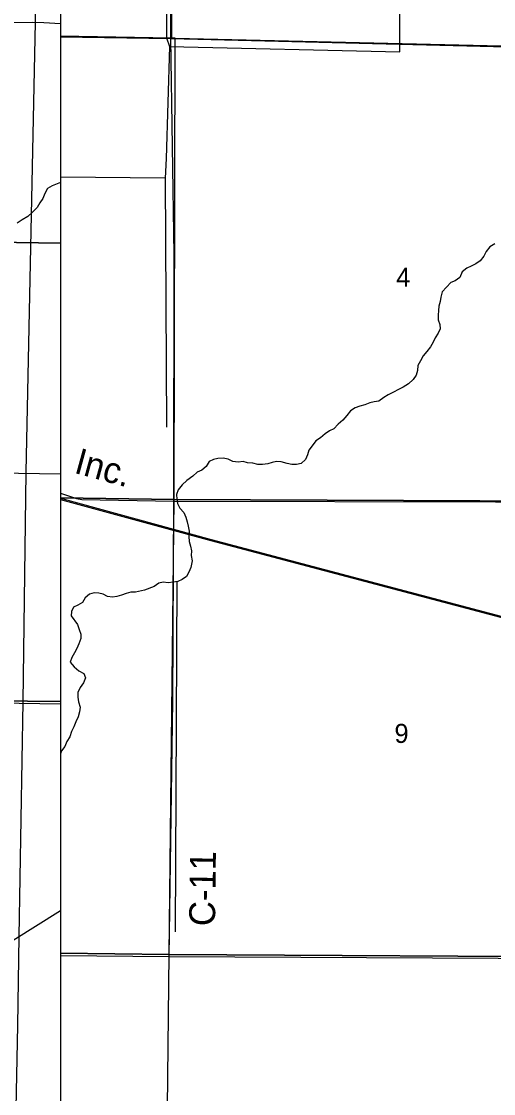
# Model space of a CAD drawing. Extents: x -6.2 to 37.4, y 0.2 to 22.2.
# Drawn here: x 5.038 to 5.556, y 16.426 to 17.601 of the extents above; entities that cross this region are included whole.
import ezdxf

# ---------------------------------------------------------------- set-up
doc = ezdxf.new("R2010")
doc.units = 0
for name, color, linetype in [('GM_X_County_Road', 7, 'Continuous'), ('GM_X_County_Road_Text', 7, 'Continuous'), ('GM_X_Minor_River', 7, 'Continuous'), ('GM_X_Rail_Line', 7, 'Continuous'), ('GM_X_Rail_Line_Text', 7, 'Continuous'), ('GM_X_Section', 7, 'Continuous'), ('GM_X_Section_Text', 7, 'Continuous'), ('GM_X_State_Route', 7, 'Continuous'), ('GM_X_Township_Road', 7, 'Continuous'), ('GM_X_US_Shield', 7, 'Continuous'), ('SH_Border', 7, 'Continuous'), ('SH_Cut_Line', 7, 'Continuous')]:
    doc.layers.add(name, color=color, linetype=linetype)

msp = doc.modelspace()

# ---------------------------------------------------------------- linework, layer by layer
at = {"layer": 'GM_X_County_Road'}
for points in [[(5.2003, 16.5759), (5.204, 16.8564), (5.2054, 17.0752), (5.2057, 17.3456), (5.202, 17.5822)], [(5.0809, 17.0839), (5.0987, 17.078), (5.1044, 17.077), (5.2054, 17.0752)], [(5.2054, 17.0752), (5.5577, 17.0744), (5.7084, 17.0732), (5.9545, 17.0713), (6.206, 17.0692)], [(4.5241, 16.8594), (4.5391, 16.8592), (4.8996, 16.8558), (5.0809, 16.853)]]:
    msp.add_lwpolyline(points, dxfattribs=at)
at = {"layer": 'GM_X_Minor_River'}
msp.add_line((5.1958, 17.4293), (5.0809, 17.4303), dxfattribs=at)
for points in [[(5.1975, 17.7074), (5.1971, 17.5832), (5.2004, 17.5735), (5.4528, 17.5676), (5.4532, 17.7074)], [(5.2004, 17.5735), (5.1968, 17.4509)], [(5.1968, 17.4509), (5.1958, 17.4293), (5.1973, 17.1562)], [(5.0809, 17.4246), (5.0773, 17.423), (5.0721, 17.421), (5.0668, 17.4179), (5.064, 17.4124), (5.0616, 17.4071), (5.0583, 17.4021), (5.0555, 17.397), (5.0505, 17.3918), (5.0451, 17.3874), (5.0392, 17.3837), (5.0336, 17.38)], [(5.5572, 17.3571), (5.5516, 17.354), (5.5474, 17.349), (5.545, 17.3437), (5.5409, 17.3387), (5.5361, 17.3352), (5.5311, 17.3328), (5.5263, 17.3304), (5.5213, 17.3266), (5.5185, 17.3205), (5.5136, 17.3167), (5.5087, 17.3147), (5.504, 17.3098), (5.4993, 17.3048), (5.4979, 17.2989), (5.497, 17.294), (5.4956, 17.2891), (5.4953, 17.284), (5.4948, 17.2789), (5.4951, 17.274), (5.4969, 17.269), (5.4972, 17.2642), (5.4948, 17.2592), (5.4917, 17.2543), (5.4895, 17.2494), (5.4865, 17.2443), (5.4824, 17.2393), (5.4785, 17.2344), (5.4756, 17.229), (5.4728, 17.2237), (5.4721, 17.2183), (5.4709, 17.2133), (5.4676, 17.2085), (5.4625, 17.2038), (5.4564, 17.2002), (5.4516, 17.1976), (5.4458, 17.1947), (5.4402, 17.1918), (5.4354, 17.1888), (5.43, 17.1849), (5.4247, 17.1839), (5.4199, 17.1831), (5.4146, 17.1807), (5.409, 17.1793), (5.4038, 17.1773), (5.399, 17.174), (5.3947, 17.169), (5.3903, 17.1639), (5.3854, 17.1597), (5.3806, 17.1546), (5.3758, 17.1523), (5.371, 17.1489), (5.3658, 17.1445), (5.3609, 17.1412), (5.357, 17.1359), (5.3533, 17.1309), (5.3517, 17.126), (5.3497, 17.1209), (5.3447, 17.1165), (5.3397, 17.1154), (5.3344, 17.1155), (5.3295, 17.1164), (5.3227, 17.1182), (5.3179, 17.1185), (5.313, 17.1177), (5.3082, 17.1159), (5.3026, 17.1152), (5.2973, 17.1155), (5.2918, 17.1168), (5.286, 17.1171), (5.2811, 17.1187), (5.2759, 17.118), (5.27, 17.1187), (5.2648, 17.1211), (5.2593, 17.1223)], [(5.2593, 17.1223), (5.2534, 17.1219), (5.2486, 17.1207), (5.2438, 17.1185), (5.2408, 17.113), (5.2358, 17.1093), (5.231, 17.107), (5.226, 17.1027), (5.2196, 17.0979), (5.2144, 17.0929), (5.2101, 17.0875), (5.2083, 17.0824), (5.2084, 17.0772), (5.2091, 17.0725), (5.2118, 17.0675), (5.2161, 17.0627), (5.2184, 17.0575), (5.2197, 17.0525), (5.2209, 17.0478), (5.2221, 17.0424), (5.2218, 17.0364), (5.2219, 17.0309), (5.2237, 17.0259), (5.2245, 17.0206), (5.2242, 17.0156), (5.2253, 17.0097), (5.2238, 17.0024), (5.2218, 16.9973), (5.2192, 16.9924), (5.2144, 16.9891), (5.2096, 16.9871), (5.2046, 16.9862), (5.1989, 16.9856), (5.1936, 16.9863), (5.1889, 16.9854), (5.1838, 16.9817), (5.1731, 16.9774), (5.1632, 16.9753), (5.1581, 16.9752), (5.1529, 16.974), (5.1479, 16.9722), (5.1428, 16.9708), (5.138, 16.9699), (5.1327, 16.9708), (5.1278, 16.9732), (5.1229, 16.9742), (5.1178, 16.9745), (5.113, 16.9733), (5.108, 16.9692), (5.105, 16.9641), (5.1002, 16.9612), (5.0952, 16.959), (5.093, 16.9541), (5.0929, 16.9494), (5.0996, 16.9398), (5.1016, 16.9346), (5.1032, 16.9294), (5.1035, 16.9247), (5.1011, 16.9189), (5.0991, 16.9138), (5.0963, 16.9087), (5.0935, 16.9038), (5.0915, 16.8986), (5.096, 16.8934), (5.101, 16.8893), (5.1065, 16.8863), (5.1085, 16.8813), (5.1061, 16.8759), (5.1026, 16.871), (5.1, 16.8654), (5.0999, 16.8603), (5.1009, 16.8553), (5.1027, 16.8492), (5.102, 16.8443), (5.1004, 16.8388), (5.098, 16.8334), (5.0956, 16.8277), (5.0932, 16.8228), (5.0912, 16.8168), (5.0881, 16.8115), (5.0857, 16.8063), (5.082, 16.8014), (5.0809, 16.7983)], [(5.2086, 16.9869), (5.2066, 16.6031)]]:
    msp.add_lwpolyline(points, dxfattribs=at)
at = {"layer": 'GM_X_Rail_Line'}
for points in [[(5.0025, 14.3074), (5.0025, 14.3335), (5.0039, 14.639), (5.0028, 14.7258), (5.0054, 14.9018), (5.0142, 15.3507), (5.0314, 16.3553), (5.0343, 16.5004), (5.0358, 16.5978), (5.0401, 16.8553), (5.0435, 17.1071), (5.0536, 17.6004), (5.0579, 17.8816), (5.0677, 18.5001), (5.0692, 18.5857), (5.0746, 18.8476), (5.0809, 19.3027)], [(7.1964, 15.5569), (7.1984, 15.7978), (7.1999, 16.0487), (7.2, 16.0578), (7.2064, 16.5582), (7.2085, 17.0529), (7.2085, 17.0597), (7.2111, 17.301), (7.2113, 17.3076), (7.2148, 17.5622), (6.712, 17.5622), (6.207, 17.5663), (5.7029, 17.5702), (5.2018, 17.5825), (5.0809, 17.5845), (5.0809, 14.5732)], [(5.0809, 17.0784), (5.2461, 17.0333), (5.5636, 16.949), (5.7619, 16.8949), (6.2912, 16.7521), (6.3632, 16.7329), (6.7711, 16.6222), (7.0142, 16.5565), (7.2044, 16.5028), (7.7111, 16.3663), (8.4626, 16.1648), (8.4809, 16.1598)], [(5.0809, 17.0771), (5.2458, 17.0321), (5.5632, 16.9478), (5.7615, 16.8937), (5.7615, 16.8937), (6.291, 16.7508), (6.363, 16.7319), (6.7708, 16.621), (6.7708, 16.621), (7.0139, 16.5552), (7.2041, 16.5016), (7.7108, 16.3651), (7.7111, 16.3663), (7.7108, 16.3651), (8.4623, 16.1636), (8.4809, 16.1586)]]:
    msp.add_lwpolyline(points, dxfattribs=at)
msp.add_lwpolyline([(7.2147, 17.7074), (5.0809, 17.7074), (5.0809, 17.5845), (5.2018, 17.5825), (5.7029, 17.5702), (6.207, 17.5663), (6.712, 17.5622), (7.2148, 17.5622)], close=True, dxfattribs=at)
at = {"layer": 'GM_X_Section'}
for points in [[(5.0809, 17.3581), (4.9115, 17.3605), (4.9235, 17.8453), (5.0809, 17.8425)], [(5.0809, 16.8554), (4.9005, 16.8573), (4.9115, 17.3605), (5.0809, 17.3581)], [(5.0809, 16.3538), (4.8912, 16.3559), (4.9005, 16.8573), (5.0809, 16.8554)]]:
    msp.add_lwpolyline(points, dxfattribs=at)
for points in [[(5.2068, 17.5826), (5.7043, 17.571), (5.7075, 17.5709), (5.7082, 17.0749), (5.2058, 17.0768)], [(5.2058, 17.0768), (5.7082, 17.0749), (5.7061, 16.5754), (5.2, 16.5783)], [(5.2, 16.5783), (5.7061, 16.5754), (5.6991, 16.0714), (5.1946, 16.0748)]]:
    msp.add_lwpolyline(points, close=True, dxfattribs=at)
at = {"layer": 'GM_X_State_Route'}
for points in [[(4.9179, 17.5894), (4.9553, 17.5929), (4.9852, 17.5957), (5.0298, 17.5999), (5.0502, 17.6003), (5.0627, 17.5999), (5.0809, 17.5988)], [(5.0809, 17.5843), (5.202, 17.5822), (5.7031, 17.57), (5.8514, 17.5675), (6.2071, 17.5661)]]:
    msp.add_lwpolyline(points, dxfattribs=at)
at = {"layer": 'GM_X_Township_Road'}
for p, q in [((5.202, 17.5822), (5.2023, 17.7074)), ((4.9055, 17.1076), (5.0809, 17.1051))]:
    msp.add_line(p, q, dxfattribs=at)
for points in [[(4.8947, 16.5761), (4.909, 16.5825), (4.9145, 16.584), (4.9249, 16.5846), (4.9765, 16.585), (5.0118, 16.5876), (5.0176, 16.5883), (5.0291, 16.5938), (5.0809, 16.6264)], [(5.0809, 16.5771), (5.2003, 16.5759), (5.7048, 16.5733), (5.951, 16.5703)]]:
    msp.add_lwpolyline(points, dxfattribs=at)
at = {"layer": 'GM_X_US_Shield'}
for points in [[(5.2029, 17.7074), (5.0809, 17.7074), (5.0809, 17.5848), (5.2027, 17.5829)], [(5.7048, 17.7074), (5.2029, 17.7074), (5.2027, 17.5829), (5.2068, 17.5826), (5.7043, 17.571)], [(5.0809, 17.5848), (5.0809, 17.0787), (5.2058, 17.0768), (5.2068, 17.5826), (5.2027, 17.5829)], [(5.0809, 17.0787), (5.0809, 16.5796), (5.2, 16.5783), (5.2058, 17.0768)], [(5.0809, 16.5796), (5.0809, 16.0763), (5.1946, 16.0748), (5.2, 16.5783)]]:
    msp.add_lwpolyline(points, close=True, dxfattribs=at)
at = {"layer": 'SH_Border'}
msp.add_line((5.0809, 21.1074), (5.0809, 14.3074), dxfattribs=at)
at = {"layer": 'SH_Cut_Line'}
msp.add_lwpolyline([(8.4809, 14.5412), (8.4809, 17.7074), (5.0809, 17.7074), (5.0809, 14.5732)], dxfattribs=at)

# ---------------------------------------------------------------- texts
at = {"layer": 'GM_X_County_Road_Text'}
msp.add_text('C-11', height=0.02841, rotation=89.3129, dxfattribs=at).set_placement((5.2504, 16.6091))
at = {"layer": 'GM_X_Rail_Line_Text'}
msp.add_text('Inc.', height=0.02831, rotation=344.6557, dxfattribs=at).set_placement((5.0949, 17.1064))
at = {"layer": 'GM_X_Section_Text'}
for s, p in [('4', (5.4489, 17.3103)), ('9', (5.447, 16.8101))]:
    msp.add_text(s, height=0.0209, rotation=0, dxfattribs=at).set_placement(p)

doc.saveas('drawing.dxf')
